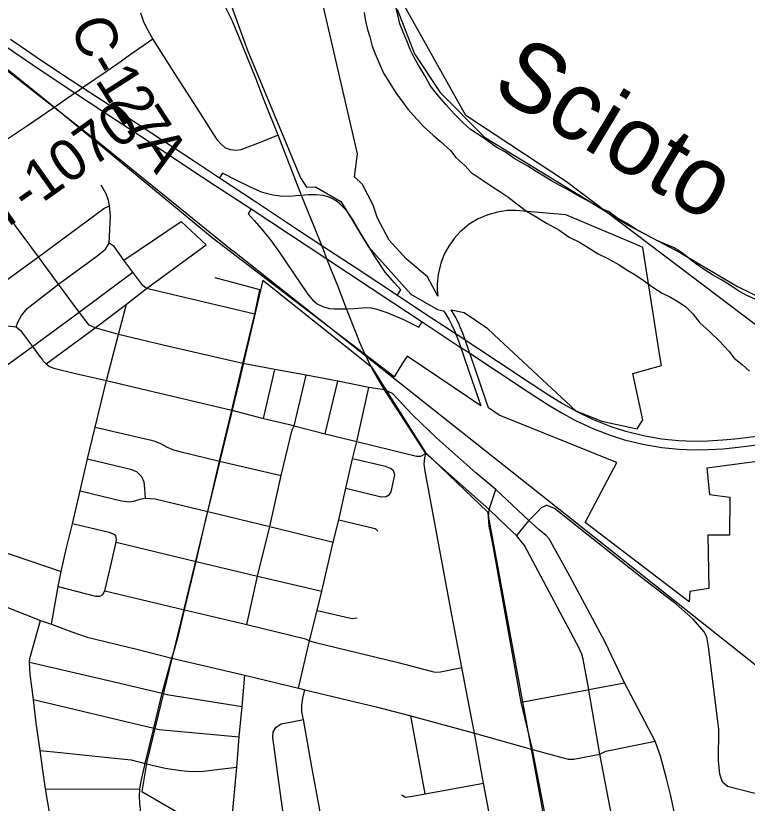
# Model space of a CAD drawing. Extents: x 0 to 34, y 0 to 22.
# Drawn here: x 3.886 to 4.895, y 14.826 to 15.912 of the extents above; entities that cross this region are included whole.
import ezdxf

# ---------------------------------------------------------------- set-up
doc = ezdxf.new("R2010")
doc.units = 0
for name, color, linetype in [('GM_X_City_Street', 7, 'Continuous'), ('GM_X_Corporation', 7, 'Continuous'), ('GM_X_County_Road', 7, 'Continuous'), ('GM_X_County_Road_Text', 7, 'Continuous'), ('GM_X_Interchange_Ramps', 7, 'Continuous'), ('GM_X_Major_River', 7, 'Continuous'), ('GM_X_Major_River_Text', 7, 'Continuous'), ('GM_X_Rail_Line', 7, 'Continuous'), ('GM_X_State_Route', 7, 'Continuous'), ('GM_X_Township_Road', 7, 'Continuous'), ('GM_X_Township_Road_Text', 7, 'Continuous'), ('GM_X_US_Route', 7, 'Continuous')]:
    doc.layers.add(name, color=color, linetype=linetype)

msp = doc.modelspace()

# ---------------------------------------------------------------- linework, layer by layer
at = {"layer": 'GM_X_City_Street'}
for p, q in [((4.2279, 15.3572), (4.2437, 15.4245)), ((4.3132, 15.336), (4.3304, 15.4086)), ((4.5394, 15.2316), (4.5483, 15.2593)), ((3.8392, 15.1834), (3.9489, 15.146)), ((4.5835, 14.9659), (4.6747, 14.9829)), ((4.451, 14.8394), (4.4314, 14.9472)), ((3.9276, 14.8464), (4.0575, 14.8457))]:
    msp.add_line(p, q, dxfattribs=at)
for points in [[(4.216, 15.5007), (4.0665, 15.5363), (4.0615, 15.5403), (4.048, 15.5588), (4.0354, 15.5752), (4.022, 15.5943), (4.0154, 15.5987), (4.017, 15.6367), (4.0155, 15.6505), (4.0143, 15.6577), (4.011, 15.6669), (4.0043, 15.6789)], [(3.7707, 15.4719), (3.7835, 15.4808), (3.8265, 15.5128), (3.874, 15.5482), (3.9175, 15.5801), (4.0078, 15.6466), (4.0155, 15.6505)], [(3.8868, 15.4833), (3.8892, 15.4897), (3.8945, 15.4989), (3.902, 15.5086), (3.9452, 15.5424), (3.9983, 15.581), (4.0101, 15.5905), (4.0154, 15.5987)], [(3.9285, 15.4326), (3.996, 15.4821), (4.039, 15.5145), (4.0665, 15.5363), (4.149, 15.5966)], [(3.8218, 15.4073), (3.8436, 15.4152), (3.8602, 15.4229), (3.8773, 15.4329), (3.9093, 15.4561), (3.9736, 15.5037), (4.048, 15.5588)], [(4.2231, 15.5344), (4.2028, 15.5402), (4.1612, 15.5509)], [(4.1996, 15.4328), (4.216, 15.5007), (4.2231, 15.5344)], [(3.8265, 15.5128), (3.8322, 15.5041), (3.8391, 15.4961), (3.8482, 15.4884), (3.8598, 15.4849), (3.875, 15.4848), (3.8868, 15.4833), (3.893, 15.4782), (3.9093, 15.4561), (3.9191, 15.4428), (3.9231, 15.4377)], [(3.9355, 15.0732), (3.9448, 15.1254), (3.9489, 15.146), (3.9562, 15.1787), (3.9644, 15.2116), (3.9751, 15.2571), (3.9854, 15.3012), (3.9961, 15.3452), (4.0114, 15.4093), (4.0279, 15.473), (4.039, 15.5145)], [(3.9231, 15.4377), (3.9243, 15.4362), (3.9285, 15.4326), (3.9328, 15.4289), (3.939, 15.4264), (3.9686, 15.4193), (4.0114, 15.4093), (4.0676, 15.3959), (4.1844, 15.3685)], [(4.2676, 15.3412), (4.2678, 15.3421), (4.2701, 15.3471), (4.287, 15.4169)], [(4.2762, 14.9849), (4.2916, 15.0504), (4.302, 15.0921), (4.3084, 15.1187), (4.3243, 15.1865), (4.3317, 15.2174), (4.3414, 15.2611), (4.3508, 15.3012), (4.3568, 15.3255), (4.3731, 15.3998)], [(4.5938, 15.2162), (4.5483, 15.2593), (4.5208, 15.2823), (4.4669, 15.3301), (4.4334, 15.3619), (4.4061, 15.3913), (4.3947, 15.3967)], [(3.9961, 15.3452), (4.0714, 15.3278), (4.0783, 15.3257), (4.0859, 15.3227), (4.0953, 15.3176), (4.1037, 15.3138), (4.1128, 15.3113), (4.1673, 15.2983), (4.2526, 15.2782)], [(4.2049, 15.0729), (4.2198, 15.1397), (4.2366, 15.208), (4.2526, 15.2782), (4.2676, 15.3412)], [(4.6124, 14.4295), (4.5968, 14.5139), (4.58, 14.597), (4.5631, 14.6874), (4.5468, 14.7746), (4.5312, 14.8543), (4.519, 14.9229), (4.5099, 14.9706), (4.5015, 15.0138), (4.4866, 15.0937), (4.451, 15.2843), (4.4494, 15.2942), (4.4505, 15.3028), (4.452, 15.3086)], [(3.9854, 15.3012), (4.0448, 15.287), (4.0531, 15.2838), (4.06, 15.2771), (4.0631, 15.2695), (4.0641, 15.2601), (4.0649, 15.247)], [(4.3414, 15.2611), (4.3903, 15.2492), (4.397, 15.2493), (4.4016, 15.2521), (4.4042, 15.256), (4.4091, 15.2794), (4.4073, 15.285), (4.4033, 15.2882), (4.3965, 15.2906), (4.3508, 15.3012)], [(3.9751, 15.2571), (4.032, 15.2435), (4.043, 15.242), (4.0506, 15.2436), (4.0578, 15.2456), (4.0649, 15.247)], [(4.0649, 15.247), (4.0788, 15.2462), (4.1512, 15.2287), (4.2366, 15.208), (4.3243, 15.1865)], [(4.5938, 15.2162), (4.6057, 15.2285), (4.6113, 15.2342), (4.6183, 15.2373)], [(4.9491, 14.8312), (4.9018, 14.8406), (4.8681, 14.8496), (4.8612, 14.8556), (4.8574, 14.8666), (4.8555, 14.8852), (4.8558, 14.9284), (4.8546, 14.9398), (4.8417, 15.042), (4.8392, 15.0561), (4.8356, 15.0627), (4.8204, 15.0805), (4.7971, 15.1008), (4.75, 15.1372), (4.6294, 15.2331), (4.6183, 15.2373)], [(4.6855, 14.4417), (4.6693, 14.5273), (4.6535, 14.6106), (4.6363, 14.7028), (4.6205, 14.7892), (4.599, 14.9005), (4.5835, 14.9659), (4.5437, 15.1863), (4.5392, 15.2087), (4.5382, 15.2211), (4.5394, 15.2316)], [(4.3317, 15.2174), (4.3822, 15.2051), (4.3859, 15.2017)], [(3.9448, 15.1254), (3.9697, 15.1189), (3.9964, 15.112), (4.0022, 15.1122), (4.0065, 15.1144), (4.0093, 15.1195), (4.0158, 15.1465), (4.0248, 15.1866), (4.0252, 15.1908), (4.0244, 15.1952), (4.0213, 15.1976), (4.0151, 15.1997), (3.9644, 15.2116)], [(4.0248, 15.1866), (4.1351, 15.1599), (4.2198, 15.1397), (4.3084, 15.1187)], [(3.7864, 15.1313), (3.795, 15.1275), (3.8131, 15.1214), (3.8298, 15.1148), (3.8762, 15.0958), (3.9206, 15.0785), (3.9355, 15.0732), (3.9638, 15.0627), (3.9848, 15.0556), (4.0534, 15.0388), (4.1014, 15.0267)], [(4.0093, 15.1195), (4.1193, 15.0933), (4.2049, 15.0729), (4.2859, 15.0533), (4.2916, 15.0504), (4.3016, 15.0475), (4.4121, 15.0208), (4.4591, 15.0087), (4.465, 15.0072), (4.4723, 15.0078), (4.5015, 15.0138)], [(4.302, 15.0921), (4.3505, 15.0811), (4.357, 15.0823)], [(3.9162, 14.9244), (3.9144, 14.937), (3.9107, 14.9694), (3.9064, 15.0044), (3.9053, 15.0208), (3.9058, 15.0259), (3.9206, 15.0785)], [(3.9053, 15.0208), (4.0204, 14.9942), (4.0883, 14.9783), (4.0948, 14.9764), (4.1984, 14.9599)], [(4.1715, 14.4578), (4.1688, 14.4908), (4.166, 14.524), (4.1641, 14.5476), (4.1631, 14.5662), (4.1679, 14.6278), (4.1702, 14.6543), (4.1711, 14.6752), (4.1761, 14.7189), (4.1793, 14.7479), (4.1859, 14.8166), (4.1911, 14.8763), (4.1945, 14.9182), (4.1984, 14.9599), (4.2021, 15.0031)], [(4.6747, 14.9829), (4.6768, 14.9833), (4.7259, 14.9924)], [(4.3202, 14.738), (4.2947, 14.8765), (4.2832, 14.9417), (4.2811, 14.9524), (4.2809, 14.9619), (4.2822, 14.9714), (4.2848, 14.9827)], [(3.9107, 14.9694), (4.0767, 14.93), (4.0841, 14.9282), (4.1945, 14.9182)], [(4.2664, 14.7311), (4.2584, 14.7897), (4.2507, 14.8459), (4.2411, 14.9172), (4.2414, 14.9248), (4.2455, 14.9315), (4.2526, 14.936), (4.2672, 14.9389), (4.2832, 14.9417)], [(3.9686, 14.6883), (3.9492, 14.736), (3.9415, 14.7566), (3.9401, 14.765), (3.9339, 14.8087), (3.9276, 14.8464), (3.9232, 14.8752), (3.9198, 14.8992), (3.9162, 14.9244)], [(3.9198, 14.8992), (3.9481, 14.8963), (4.0093, 14.8902), (4.0453, 14.8863), (4.0649, 14.8811), (4.0926, 14.875), (4.1138, 14.8714), (4.1282, 14.8704), (4.1453, 14.8708), (4.1675, 14.8732), (4.1911, 14.8763)], [(4.4189, 14.8378), (4.4235, 14.835), (4.4337, 14.8362), (4.451, 14.8394), (4.5312, 14.8543)]]:
    msp.add_lwpolyline(points, dxfattribs=at)
at = {"layer": 'GM_X_Corporation'}
msp.add_lwpolyline([(4.954, 16.5082), (5.5235, 16.4744), (5.4838, 15.928), (5.1703, 15.9522), (5.1154, 15.3283), (4.6458, 15.6833), (4.5069, 15.7747), (4.4145, 15.9403), (4.4603, 16.1602), (4.6083, 16.3799), (4.6463, 16.394)], close=True, dxfattribs=at)
for points in [[(4.1764, 15.9463), (4.2064, 15.8637), (4.2789, 15.6888), (4.2874, 15.6761), (4.2997, 15.6767), (4.3348, 15.6565), (4.3403, 15.6474), (4.3724, 15.594), (4.4312, 15.5286), (4.4681, 15.5073), (4.4762, 15.5056), (4.4784, 15.5023), (4.4811, 15.4979), (4.4839, 15.493), (4.4876, 15.4859), (4.4918, 15.4769), (4.4972, 15.4628), (4.5112, 15.4221), (4.5276, 15.3744), (4.4699, 15.4134), (4.4261, 15.443), (4.4196, 15.4334), (4.4082, 15.4147), (4.1571, 15.6063), (3.9424, 15.7834), (3.6542, 16.0168)], [(5.0131, 15.3117), (4.8395, 15.2884), (4.843, 15.2524), (4.8713, 15.2487), (4.8705, 15.196), (4.8406, 15.1959), (4.8422, 15.1227), (4.816, 15.1183), (4.8151, 15.1043), (4.6716, 15.2138), (4.6901, 15.2485), (4.7154, 15.2962), (4.7092, 15.2987), (4.553, 15.3618), (4.5384, 15.3716), (4.5357, 15.3796), (4.5189, 15.4282), (4.5066, 15.4642), (4.5028, 15.4747), (4.4994, 15.483), (4.4978, 15.4868), (4.495, 15.4926), (4.4923, 15.4977), (4.4896, 15.5025), (4.487, 15.5069), (4.5048, 15.5032), (4.5362, 15.482), (4.5462, 15.4726), (4.5926, 15.4294), (4.6586, 15.3678), (4.6946, 15.3532), (4.7435, 15.3428), (4.7512, 15.355), (4.7375, 15.4193), (4.7768, 15.4299), (4.7743, 15.4461), (4.751, 15.593), (4.7388, 15.5982), (4.6452, 15.6379), (4.576, 15.6439), (4.5647, 15.6437), (4.5506, 15.6417), (4.5376, 15.6381), (4.5243, 15.6324), (4.5117, 15.6248), (4.4987, 15.6139), (4.4909, 15.6053), (4.4834, 15.5948), (4.4773, 15.5835), (4.4725, 15.5714), (4.4688, 15.5557), (4.4676, 15.5429), (4.4676, 15.5341), (4.4684, 15.5256), (4.4542, 15.5524), (4.4246, 15.5772), (4.4015, 15.6029), (4.3852, 15.6332), (4.3793, 15.6512), (4.3647, 15.6799), (4.3533, 15.6901), (4.3578, 15.722), (4.311, 15.9248)], [(4.4125, 15.9213), (4.4361, 15.86), (4.4716, 15.8066), (4.5327, 15.745), (4.6343, 15.6831), (4.7318, 15.6231), (4.8029, 15.5857), (4.8816, 15.5392), (4.9543, 15.5037)]]:
    msp.add_lwpolyline(points, dxfattribs=at)
at = {"layer": 'GM_X_County_Road'}
for p, q in [((4.5895, 15.2108), (4.5771, 15.1955)), ((4.7002, 14.8982), (4.7681, 14.9121))]:
    msp.add_line(p, q, dxfattribs=at)
for points in [[(4.2483, 15.7476), (4.2233, 15.7375), (4.1967, 15.7274), (4.1897, 15.7267), (4.1823, 15.7277), (4.1754, 15.73), (4.1693, 15.7358), (4.1651, 15.7406), (4.158, 15.751), (4.1406, 15.7787), (4.1088, 15.8279), (4.0755, 15.8808), (4.0675, 15.8942), (4.0624, 15.9049), (4.0587, 15.916)], [(4.1496, 15.2218), (4.1512, 15.2287), (4.1673, 15.2983), (4.1844, 15.3685), (4.1996, 15.4328)], [(4.1844, 15.3685), (4.2279, 15.3572), (4.2641, 15.3486)], [(4.2641, 15.3486), (4.2701, 15.3471), (4.3132, 15.336), (4.3568, 15.3255), (4.4056, 15.3134), (4.439, 15.3053), (4.4452, 15.3051), (4.452, 15.3086)], [(4.1014, 15.0267), (4.1057, 15.0399), (4.1114, 15.0599), (4.1193, 15.0933), (4.1351, 15.1599), (4.1496, 15.2218)], [(4.7259, 14.9924), (4.6994, 15.0486), (4.6505, 15.1397), (4.6221, 15.1909), (4.618, 15.1958), (4.6081, 15.2036), (4.5938, 15.2162), (4.5895, 15.2108)], [(4.0738, 14.7028), (4.0672, 14.7528), (4.0594, 14.8081), (4.0573, 14.8265), (4.057, 14.8359), (4.0575, 14.8457), (4.0588, 14.8546), (4.0649, 14.8811), (4.0767, 14.93), (4.0883, 14.9783), (4.1014, 15.0267)], [(4.1014, 15.0267), (4.2021, 15.0031), (4.2762, 14.9849), (4.2848, 14.9827), (4.3832, 14.9596), (4.4314, 14.9472), (4.519, 14.9229), (4.599, 14.9005), (4.6411, 14.8892), (4.6481, 14.8871), (4.6559, 14.8872), (4.6918, 14.8941), (4.6992, 14.898), (4.7002, 14.8982)], [(4.8104, 14.7349), (4.7928, 14.8216), (4.7894, 14.8387), (4.7839, 14.8605), (4.7754, 14.8913), (4.7681, 14.9121), (4.7259, 14.9924)]]:
    msp.add_lwpolyline(points, dxfattribs=at)
at = {"layer": 'GM_X_Interchange_Ramps'}
msp.add_line((4.3817, 15.5804), (4.376, 15.5897), dxfattribs=at)
for points in [[(4.2805, 15.6644), (4.2728, 15.6641), (4.2638, 15.6633), (4.2509, 15.6635), (4.2408, 15.6648), (4.2268, 15.6689), (4.2112, 15.6755), (4.1904, 15.6856), (4.1714, 15.6955), (4.1675, 15.6888)], [(4.3412, 15.6454), (4.3331, 15.6532), (4.3283, 15.657), (4.3224, 15.6603), (4.3171, 15.6626), (4.3104, 15.6647), (4.3007, 15.6657), (4.2898, 15.6654), (4.2805, 15.6644)], [(4.2109, 15.646), (4.2071, 15.6392), (4.2153, 15.6301), (4.2254, 15.6184), (4.2387, 15.6021), (4.2492, 15.5874), (4.2686, 15.5587), (4.2798, 15.5419), (4.2901, 15.5273), (4.293, 15.5237)], [(4.376, 15.5897), (4.3596, 15.6166), (4.3509, 15.6317), (4.342, 15.6446), (4.3412, 15.6454)], [(4.4126, 15.5271), (4.4172, 15.5345), (4.4086, 15.544), (4.396, 15.5588), (4.3834, 15.5776), (4.3817, 15.5804)], [(4.293, 15.5237), (4.2959, 15.5201), (4.3022, 15.5152), (4.3108, 15.511), (4.3191, 15.5087), (4.3254, 15.5081), (4.3364, 15.5083), (4.3424, 15.5084)], [(4.3424, 15.5084), (4.3525, 15.5087), (4.3695, 15.51), (4.3765, 15.5095), (4.383, 15.5082), (4.3994, 15.5028), (4.4212, 15.4936), (4.4424, 15.4831), (4.4469, 15.4902)]]:
    msp.add_lwpolyline(points, dxfattribs=at)
at = {"layer": 'GM_X_Major_River'}
for points in [[(4.715, 15.6344), (4.7037, 15.6427), (4.6919, 15.6473), (4.6787, 15.6553), (4.6606, 15.6648), (4.6473, 15.6728), (4.6368, 15.6785), (4.6254, 15.6849), (4.6145, 15.6914), (4.6042, 15.6978), (4.5925, 15.7051), (4.5736, 15.7157), (4.5619, 15.7241), (4.5487, 15.7313), (4.5317, 15.7434), (4.5135, 15.7556), (4.5033, 15.7647), (4.4909, 15.7773), (4.4796, 15.7902), (4.4656, 15.8061), (4.458, 15.8164), (4.4509, 15.8293), (4.4418, 15.8441), (4.4358, 15.8547), (4.4305, 15.8661), (4.4264, 15.8755), (4.4207, 15.8896), (4.4162, 15.9013), (4.4136, 15.912), (4.4106, 15.9245)], [(4.3667, 15.917), (4.3689, 15.9052), (4.3715, 15.8934), (4.3746, 15.8836), (4.3779, 15.8707), (4.3821, 15.8597), (4.3877, 15.8472), (4.3934, 15.8331), (4.4024, 15.8195), (4.4107, 15.8062), (4.4198, 15.7937), (4.4269, 15.7838), (4.4401, 15.7694), (4.4485, 15.7599), (4.462, 15.7477), (4.4719, 15.739), (4.4858, 15.7264), (4.4934, 15.717), (4.5055, 15.7059), (4.5145, 15.6965), (4.5308, 15.6854), (4.5425, 15.6775), (4.5538, 15.6702), (4.5652, 15.6626), (4.5773, 15.6531), (4.5909, 15.6429), (4.6049, 15.6345), (4.6185, 15.6265), (4.6351, 15.617), (4.6495, 15.6072), (4.6638, 15.6003), (4.6771, 15.5919), (4.6895, 15.5843), (4.7031, 15.5775), (4.7186, 15.5691), (4.7307, 15.5612), (4.7417, 15.5547), (4.7515, 15.5479), (4.7651, 15.538), (4.7776, 15.53), (4.7886, 15.5247), (4.7995, 15.5186), (4.8101, 15.5114), (4.8199, 15.5015), (4.8297, 15.489), (4.8429, 15.4772), (4.8569, 15.4635), (4.8698, 15.4499), (4.8773, 15.4404), (4.8883, 15.4313), (4.8981, 15.4221)], [(4.9063, 15.5215), (4.8945, 15.5268), (4.8821, 15.5336), (4.8692, 15.5424), (4.8586, 15.5485), (4.8473, 15.5553), (4.8371, 15.5618), (4.8223, 15.5716), (4.8053, 15.5857), (4.7933, 15.5929), (4.7823, 15.5975), (4.7694, 15.6028), (4.7543, 15.6112), (4.7437, 15.6169), (4.7286, 15.6264), (4.715, 15.6344)]]:
    msp.add_lwpolyline(points, dxfattribs=at)
at = {"layer": 'GM_X_Rail_Line'}
for points in [[(2.1, 16.8228), (2.1358, 16.8282), (2.1875, 16.8321), (2.2635, 16.8323), (2.3249, 16.8251), (2.3996, 16.8184), (2.4546, 16.8097), (2.5216, 16.7954), (2.5976, 16.772), (2.6544, 16.7517), (2.7256, 16.7157), (2.7928, 16.6809), (2.8517, 16.6435), (2.9129, 16.5996), (3.0775, 16.4694), (3.2031, 16.3691), (3.3322, 16.2662), (3.4651, 16.1627), (3.5695, 16.0783), (3.7315, 15.9489), (3.9997, 15.7391), (4.1856, 15.5884)], [(5.4414, 14.6296), (5.3773, 14.6666), (5.3234, 14.6984), (5.22, 14.7677), (5.0975, 14.8655), (4.6196, 15.2442), (4.1856, 15.5884)], [(4.2271, 15.5477), (4.1947, 15.4102), (4.0672, 14.8839), (4.0604, 14.8428), (4.1093, 14.8143), (4.1562, 14.7972), (4.1796, 14.7326), (4.1656, 14.561), (4.1712, 14.4975), (4.1736, 14.4595), (4.2142, 14.4574), (4.4075, 14.4723), (4.4677, 14.4671), (4.5199, 14.4589), (4.5645, 14.4425), (4.6117, 14.4149), (4.8025, 14.2772), (5.1384, 14.3395)], [(4.2271, 15.5477), (4.3769, 15.4282), (4.3992, 15.3927), (4.4515, 15.3102), (4.5368, 15.2281), (4.6187, 14.7836), (4.6868, 14.4421), (4.9407, 14.4928), (4.9555, 14.4019), (5.1218, 14.4332), (5.1384, 14.3395)]]:
    msp.add_lwpolyline(points, dxfattribs=at)
at = {"layer": 'GM_X_State_Route'}
for p, q in [((4.2483, 15.7476), (4.2305, 15.7922)), ((4.2805, 15.6644), (4.2483, 15.7476)), ((4.5394, 15.2316), (4.4593, 15.3022))]:
    msp.add_line(p, q, dxfattribs=at)
for points in [[(4.2305, 15.7922), (4.2277, 15.7993), (4.2178, 15.8251), (4.1933, 15.886), (4.1847, 15.906), (4.1759, 15.9235), (4.1673, 15.9393), (4.159, 15.9522), (4.1499, 15.9655)], [(4.3101, 15.591), (4.3084, 15.5956), (4.2986, 15.6196), (4.2805, 15.6644)], [(4.3208, 15.5635), (4.3152, 15.5772), (4.3101, 15.591)], [(4.3575, 15.4703), (4.3424, 15.5084), (4.3306, 15.5398), (4.3208, 15.5635)], [(4.3697, 15.4419), (4.3605, 15.4627), (4.3575, 15.4703)], [(4.4593, 15.3022), (4.452, 15.3086), (4.4224, 15.3541), (4.3947, 15.3967), (4.3779, 15.4258), (4.3697, 15.4419)], [(4.6769, 14.9823), (4.6768, 14.9833), (4.6689, 15.0252), (4.667, 15.0322), (4.6634, 15.0403), (4.5878, 15.182), (4.5771, 15.1955), (4.5636, 15.208), (4.5394, 15.2316)], [(4.8119, 14.2779), (4.7927, 14.369), (4.7757, 14.4577), (4.7428, 14.6271), (4.7254, 14.7201), (4.709, 14.8059), (4.6918, 14.8941), (4.6769, 14.9823)]]:
    msp.add_lwpolyline(points, dxfattribs=at)
at = {"layer": 'GM_X_Township_Road'}
for points in [[(4.0322, 15.8505), (4.0443, 15.859), (4.0755, 15.8808)], [(3.9723, 15.8091), (3.9784, 15.8135), (4.0123, 15.8366), (4.0322, 15.8505)], [(3.9374, 15.7851), (3.9679, 15.806), (3.9723, 15.8091)], [(3.8068, 15.6975), (3.8216, 15.708), (3.8619, 15.7345), (3.9026, 15.7612), (3.9374, 15.7851)], [(4.0279, 15.473), (3.996, 15.4821), (3.9877, 15.4858), (3.9736, 15.5037), (3.9452, 15.5424), (3.9175, 15.5801), (3.8859, 15.6225), (3.851, 15.6691), (3.8466, 15.6749)], [(4.0354, 15.5752), (4.1143, 15.6285), (4.149, 15.5966)], [(4.1996, 15.4328), (4.0973, 15.4564), (4.0279, 15.473)], [(4.3947, 15.3967), (4.3731, 15.3998), (4.3304, 15.4086), (4.287, 15.4169), (4.2437, 15.4245), (4.1996, 15.4328)]]:
    msp.add_lwpolyline(points, dxfattribs=at)
at = {"layer": 'GM_X_US_Route'}
msp.add_line((4.5056, 15.4515), (4.514, 15.446), dxfattribs=at)
for points in [[(3.3015, 16.3185), (3.3261, 16.2986), (3.3859, 16.2513), (3.4634, 16.1898), (3.5529, 16.1188), (3.6365, 16.0523), (3.7083, 15.9956), (3.7739, 15.9433), (3.8407, 15.8928), (3.8734, 15.8696), (3.9099, 15.8447), (3.9477, 15.8195), (3.9679, 15.806), (4.0109, 15.7777), (4.068, 15.7402), (4.1251, 15.7023), (4.1616, 15.6785), (4.2109, 15.646), (4.3152, 15.5772), (4.4063, 15.5171), (4.4469, 15.4902), (4.4981, 15.4565), (4.5056, 15.4515)], [(3.8793, 15.88), (3.9158, 15.8551), (3.9536, 15.8298), (3.9784, 15.8135), (4.0138, 15.7903), (4.0392, 15.7736), (4.0739, 15.7506), (4.1341, 15.711), (4.1675, 15.6888), (4.2156, 15.657), (4.2292, 15.6481), (4.2736, 15.6188), (4.3084, 15.5956), (4.3557, 15.5647), (4.4126, 15.5271), (4.4506, 15.502), (4.495, 15.4727), (4.552, 15.435), (4.5958, 15.4061), (4.6213, 15.3895), (4.6406, 15.3776), (4.6602, 15.3667), (4.6817, 15.3562), (4.7069, 15.3461), (4.7258, 15.3401), (4.7523, 15.3334), (4.7769, 15.3289), (4.8002, 15.3267), (4.8214, 15.3258), (4.8408, 15.3262), (4.8613, 15.3275), (4.8779, 15.329), (4.8938, 15.3308), (4.9785, 15.3418)], [(4.514, 15.446), (4.5929, 15.3939), (4.6191, 15.3768), (4.6385, 15.3651), (4.6584, 15.3543), (4.6822, 15.3431), (4.7073, 15.3334), (4.7261, 15.3275), (4.7512, 15.3214), (4.7774, 15.3168), (4.8007, 15.3146), (4.822, 15.3137), (4.8413, 15.3141), (4.8618, 15.3154), (4.8784, 15.3169), (4.8943, 15.3188), (4.9791, 15.3298), (5.0624, 15.3407), (5.1506, 15.3524), (5.2708, 15.3683), (5.3195, 15.3747), (5.4294, 15.3891)]]:
    msp.add_lwpolyline(points, dxfattribs=at)

# ---------------------------------------------------------------- texts
at = {"layer": 'GM_X_County_Road_Text'}
for s, rotation, p in [('C', 288.8003, (3.9617, 15.9012)), ('-', 300.3219, (3.9819, 15.8457)), ('1', 302.5, (3.9949, 15.8235)), ('2', 303.0338, (4.014, 15.7935)), ('7', 303.08, (4.0331, 15.7641)), ('A', 303.4456, (4.0525, 15.7345))]:
    msp.add_text(s, height=0.0568, rotation=rotation, dxfattribs=at).set_placement(p)
at = {"layer": 'GM_X_Major_River_Text'}
msp.add_text('Scioto', height=0.0947, rotation=328.9966, dxfattribs=at).set_placement((4.5396, 15.8077))
at = {"layer": 'GM_X_Township_Road_Text'}
msp.add_text('T-1070', height=0.05682, rotation=35.3156, dxfattribs=at).set_placement((3.8645, 15.6124))

doc.saveas('drawing.dxf')
